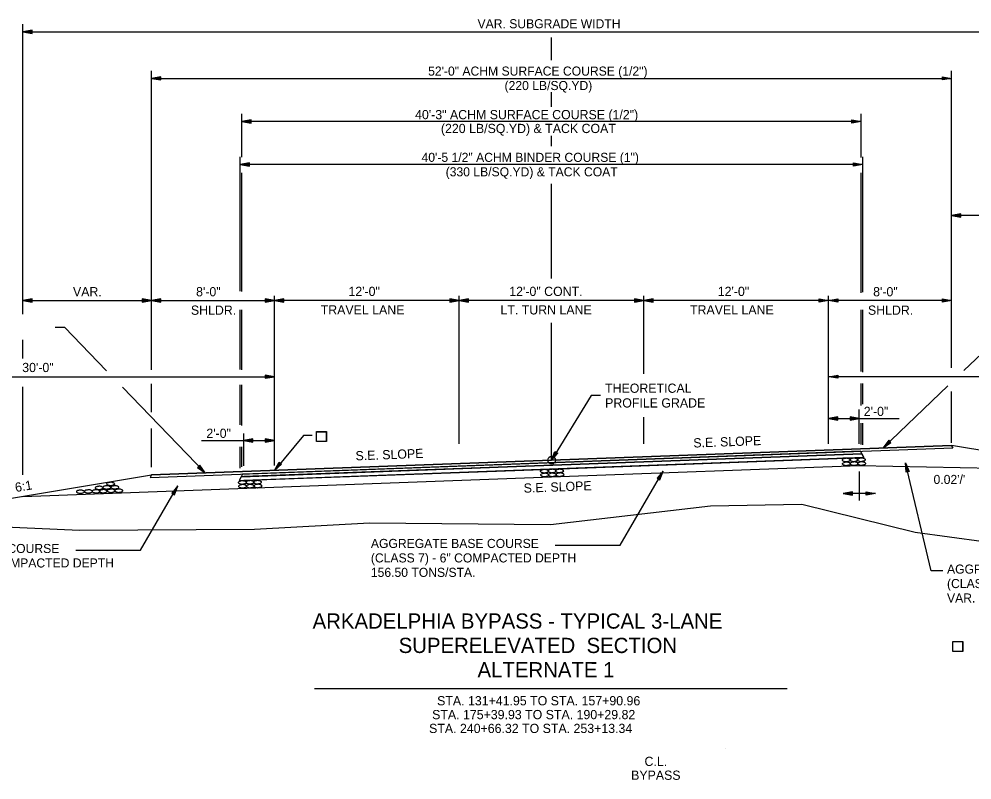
# Model space of a CAD drawing. Extents: x 1001270 to 1003428, y 1840152 to 1842912.
# Drawn here: x 1002308.4 to 1002370.3, y 1842569.6 to 1842619.1 of the extents above; entities that cross this region are included whole.
import ezdxf

# ---------------------------------------------------------------- set-up
doc = ezdxf.new("R2010")
doc.units = 0
for name, color, linetype in [('1', 7, 'Continuous'), ('19', 7, 'Continuous'), ('G-Table-Minor', 7, 'Continuous'), ('Level 1', 7, 'Continuous')]:
    doc.layers.add(name, color=color, linetype=linetype)

# ---------------------------------------------------------------- blocks, each defined once
blk = doc.blocks.new('ROCKS')
at = {"layer": '1'}
blk.add_spline([(0.013, 0.06), (0.053, 0.053), (0.107, 0.033), (0.133, 0.013), (0.133, -0.007), (0.12, -0.033), (0.107, -0.04), (0.073, -0.053), (0.033, -0.067), (0.013, -0.067), (-0.02, -0.06), (-0.06, -0.053), (-0.087, -0.047), (-0.113, -0.02), (-0.113, -0.007), (-0.107, 0.02), (-0.087, 0.033), (-0.067, 0.047), (-0.033, 0.053), (-0.02, 0.06), (0.013, 0.06)], degree=3, dxfattribs=at)
blk = doc.blocks.new('4TO1 ABC')
at = {"layer": '1', "xscale": 0.1312491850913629, "yscale": 0.1312491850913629, "rotation": 180}
for p in [(0.00175, -0.00875), (-0.03325, -0.0385), (-0.016625, -0.023625), (0, -0.0385), (0.018375, -0.023625), (0.034125, -0.04025), (0.051625, -0.025375), (0.06475, -0.04025), (0.098, -0.04025), (0.133, -0.041125)]:
    blk.add_blockref('ROCKS', p, dxfattribs=at)

msp = doc.modelspace()

# ---------------------------------------------------------------- linework, layer by layer
at = {"layer": '19'}
for p, q in [((1002308.637, 1842599.91), (1002308.637, 1842618.76)), ((1002309.237, 1842618.365), (1002308.637, 1842618.26)), ((1002308.637, 1842618.26), (1002378.71, 1842618.26)), ((1002308.637, 1842618.26), (1002309.237, 1842618.155)), ((1002309.237, 1842618.31), (1002308.797, 1842618.275)), ((1002308.797, 1842618.245), (1002309.237, 1842618.205)), ((1002309.237, 1842618.155), (1002309.237, 1842618.365)), ((1002342.992, 1842616.409), (1002342.992, 1842617.891)), ((1002316.992, 1842598.095), (1002316.992, 1842615.733)), ((1002368.992, 1842597.704), (1002368.992, 1842615.733)), ((1002317.592, 1842615.338), (1002316.992, 1842615.233)), ((1002316.992, 1842615.233), (1002317.592, 1842615.128)), ((1002316.992, 1842615.233), (1002368.992, 1842615.233)), ((1002317.592, 1842615.283), (1002317.152, 1842615.248)), ((1002317.152, 1842615.218), (1002317.592, 1842615.178)), ((1002317.592, 1842615.128), (1002317.592, 1842615.338)), ((1002368.392, 1842615.128), (1002368.392, 1842615.338)), ((1002368.392, 1842615.338), (1002368.992, 1842615.233)), ((1002368.392, 1842615.283), (1002368.832, 1842615.248)), ((1002368.992, 1842615.233), (1002368.392, 1842615.128)), ((1002368.832, 1842615.218), (1002368.392, 1842615.178)), ((1002342.992, 1842613.372), (1002342.992, 1842614.336)), ((1002322.864, 1842610.118), (1002322.864, 1842612.926)), ((1002363.119, 1842610.079), (1002363.119, 1842612.926)), ((1002323.464, 1842612.531), (1002322.864, 1842612.426)), ((1002322.864, 1842612.426), (1002323.464, 1842612.321)), ((1002363.119, 1842612.426), (1002322.864, 1842612.426)), ((1002323.464, 1842612.476), (1002323.024, 1842612.441)), ((1002323.024, 1842612.411), (1002323.464, 1842612.371)), ((1002323.464, 1842612.321), (1002323.464, 1842612.531)), ((1002362.519, 1842612.321), (1002362.519, 1842612.531)), ((1002362.519, 1842612.531), (1002363.119, 1842612.426)), ((1002362.519, 1842612.476), (1002362.959, 1842612.441)), ((1002363.119, 1842612.426), (1002362.519, 1842612.321)), ((1002362.959, 1842612.411), (1002362.519, 1842612.371)), ((1002342.992, 1842610.821), (1002342.992, 1842611.5)), ((1002322.758, 1842601.407), (1002322.758, 1842610.127)), ((1002363.226, 1842601.334), (1002363.226, 1842610.127)), ((1002323.358, 1842609.732), (1002322.758, 1842609.627)), ((1002322.758, 1842609.627), (1002323.358, 1842609.522)), ((1002363.226, 1842609.627), (1002322.758, 1842609.627)), ((1002323.358, 1842609.677), (1002322.918, 1842609.642)), ((1002322.918, 1842609.612), (1002323.358, 1842609.572)), ((1002323.358, 1842609.522), (1002323.358, 1842609.732)), ((1002362.626, 1842609.522), (1002362.626, 1842609.732)), ((1002362.626, 1842609.732), (1002363.226, 1842609.627)), ((1002362.626, 1842609.677), (1002363.066, 1842609.642)), ((1002363.226, 1842609.627), (1002362.626, 1842609.522)), ((1002363.066, 1842609.612), (1002362.626, 1842609.572)), ((1002322.864, 1842601.383), (1002322.864, 1842609.094)), ((1002363.119, 1842601.286), (1002363.119, 1842609.094)), ((1002342.992, 1842602.217), (1002342.992, 1842608.384)), ((1002369.592, 1842606.423), (1002368.992, 1842606.318)), ((1002369.592, 1842606.368), (1002369.152, 1842606.333)), ((1002369.592, 1842606.213), (1002369.592, 1842606.423)), ((1002378.71, 1842606.318), (1002368.992, 1842606.318)), ((1002368.992, 1842606.318), (1002369.592, 1842606.213)), ((1002369.152, 1842606.303), (1002369.592, 1842606.263)), ((1002377.255, 1842603.38), (1002369.786, 1842596.23)), ((1002309.236, 1842600.889), (1002308.636, 1842600.784)), ((1002309.236, 1842600.834), (1002308.796, 1842600.799)), ((1002309.236, 1842600.679), (1002309.236, 1842600.889)), ((1002316.392, 1842600.889), (1002316.392, 1842600.679)), ((1002316.992, 1842600.784), (1002316.392, 1842600.889)), ((1002316.832, 1842600.799), (1002316.392, 1842600.834)), ((1002316.992, 1842596.29), (1002316.992, 1842601.084)), ((1002317.592, 1842600.889), (1002316.992, 1842600.784)), ((1002317.592, 1842600.834), (1002317.152, 1842600.799)), ((1002317.592, 1842600.679), (1002317.592, 1842600.889)), ((1002324.392, 1842600.889), (1002324.392, 1842600.679)), ((1002324.992, 1842600.784), (1002324.392, 1842600.889)), ((1002324.832, 1842600.799), (1002324.392, 1842600.834)), ((1002324.992, 1842590.065), (1002324.992, 1842601.084)), ((1002325.592, 1842600.889), (1002324.992, 1842600.784)), ((1002325.592, 1842600.834), (1002325.152, 1842600.799)), ((1002325.592, 1842600.679), (1002325.592, 1842600.889)), ((1002336.392, 1842600.889), (1002336.392, 1842600.679)), ((1002336.992, 1842600.784), (1002336.392, 1842600.889)), ((1002336.832, 1842600.799), (1002336.392, 1842600.834)), ((1002336.992, 1842591.469), (1002336.992, 1842601.084)), ((1002337.592, 1842600.889), (1002336.992, 1842600.784)), ((1002337.592, 1842600.834), (1002337.152, 1842600.799)), ((1002337.592, 1842600.679), (1002337.592, 1842600.889)), ((1002348.392, 1842600.889), (1002348.392, 1842600.679)), ((1002348.992, 1842600.784), (1002348.392, 1842600.889)), ((1002348.832, 1842600.799), (1002348.392, 1842600.834)), ((1002348.992, 1842596.027), (1002348.992, 1842601.084)), ((1002349.592, 1842600.889), (1002348.992, 1842600.784)), ((1002349.592, 1842600.834), (1002349.152, 1842600.799)), ((1002349.592, 1842600.679), (1002349.592, 1842600.889)), ((1002360.392, 1842600.679), (1002360.392, 1842600.889)), ((1002360.392, 1842600.889), (1002360.992, 1842600.784)), ((1002360.392, 1842600.834), (1002360.832, 1842600.799)), ((1002360.992, 1842591.469), (1002360.992, 1842601.084)), ((1002360.992, 1842600.784), (1002361.592, 1842600.889)), ((1002361.152, 1842600.799), (1002361.592, 1842600.834)), ((1002361.592, 1842600.889), (1002361.592, 1842600.679)), ((1002368.392, 1842600.679), (1002368.392, 1842600.889)), ((1002368.392, 1842600.889), (1002368.992, 1842600.784)), ((1002368.392, 1842600.834), (1002368.832, 1842600.799)), ((1002368.992, 1842596.416), (1002368.992, 1842601.084)), ((1002308.636, 1842600.784), (1002309.236, 1842600.679)), ((1002308.637, 1842600.784), (1002324.992, 1842600.784)), ((1002308.796, 1842600.769), (1002309.236, 1842600.729)), ((1002316.392, 1842600.679), (1002316.992, 1842600.784)), ((1002316.392, 1842600.729), (1002316.832, 1842600.769)), ((1002316.992, 1842600.784), (1002317.592, 1842600.679)), ((1002317.152, 1842600.769), (1002317.592, 1842600.729)), ((1002322.758, 1842596.313), (1002322.758, 1842600.194)), ((1002322.864, 1842596.284), (1002322.864, 1842600.194)), ((1002324.392, 1842600.679), (1002324.992, 1842600.784)), ((1002324.392, 1842600.729), (1002324.832, 1842600.769)), ((1002324.992, 1842600.784), (1002325.592, 1842600.679)), ((1002336.992, 1842600.784), (1002324.992, 1842600.784)), ((1002325.152, 1842600.769), (1002325.592, 1842600.729)), ((1002336.392, 1842600.679), (1002336.992, 1842600.784)), ((1002336.392, 1842600.729), (1002336.832, 1842600.769)), ((1002348.992, 1842600.784), (1002336.992, 1842600.784)), ((1002336.992, 1842600.784), (1002337.592, 1842600.679)), ((1002337.152, 1842600.769), (1002337.592, 1842600.729)), ((1002348.392, 1842600.679), (1002348.992, 1842600.784)), ((1002348.392, 1842600.729), (1002348.832, 1842600.769)), ((1002360.992, 1842600.784), (1002348.992, 1842600.784)), ((1002348.992, 1842600.784), (1002349.592, 1842600.679)), ((1002349.152, 1842600.769), (1002349.592, 1842600.729)), ((1002360.992, 1842600.784), (1002360.392, 1842600.679)), ((1002360.832, 1842600.769), (1002360.392, 1842600.729)), ((1002368.992, 1842600.784), (1002360.992, 1842600.784)), ((1002361.592, 1842600.679), (1002360.992, 1842600.784)), ((1002361.592, 1842600.729), (1002361.152, 1842600.769)), ((1002363.119, 1842596.169), (1002363.119, 1842600.194)), ((1002363.226, 1842596.14), (1002363.226, 1842600.194)), ((1002368.992, 1842600.784), (1002368.392, 1842600.679)), ((1002368.832, 1842600.769), (1002368.392, 1842600.729)), ((1002342.992, 1842590.412), (1002342.992, 1842599.341)), ((1002308.637, 1842597.021), (1002308.637, 1842598.235)), ((1002294.986, 1842595.836), (1002324.986, 1842595.836)), ((1002324.386, 1842595.941), (1002324.386, 1842595.731)), ((1002324.986, 1842595.836), (1002324.386, 1842595.941)), ((1002324.826, 1842595.851), (1002324.386, 1842595.886)), ((1002324.386, 1842595.731), (1002324.986, 1842595.836)), ((1002361.009, 1842595.836), (1002361.609, 1842595.941)), ((1002391.009, 1842595.836), (1002361.009, 1842595.836)), ((1002361.609, 1842595.731), (1002361.009, 1842595.836)), ((1002361.169, 1842595.851), (1002361.609, 1842595.886)), ((1002361.609, 1842595.941), (1002361.609, 1842595.731)), ((1002316.992, 1842593.539), (1002316.992, 1842595.371)), ((1002322.758, 1842592.701), (1002322.758, 1842595.302)), ((1002322.864, 1842592.672), (1002322.864, 1842595.302)), ((1002324.386, 1842595.781), (1002324.826, 1842595.821)), ((1002361.609, 1842595.781), (1002361.169, 1842595.821)), ((1002363.119, 1842593.973), (1002363.119, 1842595.388)), ((1002363.226, 1842594.059), (1002363.226, 1842595.388)), ((1002368.754, 1842595.241), (1002364.542, 1842591.209)), ((1002308.637, 1842589.451), (1002308.637, 1842595.172)), ((1002368.992, 1842591.535), (1002368.992, 1842594.882)), ((1002362.992, 1842591.469), (1002362.992, 1842593.707)), ((1002348.992, 1842591.469), (1002348.992, 1842593.213)), ((1002361.592, 1842593.221), (1002360.992, 1842593.116)), ((1002360.992, 1842593.116), (1002365.578, 1842593.116)), ((1002360.992, 1842593.116), (1002361.592, 1842593.011)), ((1002361.592, 1842593.166), (1002361.152, 1842593.131)), ((1002361.152, 1842593.101), (1002361.592, 1842593.061)), ((1002361.592, 1842593.011), (1002361.592, 1842593.221)), ((1002362.392, 1842593.221), (1002362.392, 1842593.011)), ((1002362.992, 1842593.116), (1002362.392, 1842593.221)), ((1002362.832, 1842593.131), (1002362.392, 1842593.166)), ((1002362.392, 1842593.011), (1002362.992, 1842593.116)), ((1002362.392, 1842593.061), (1002362.832, 1842593.101)), ((1002363.119, 1842591.43), (1002363.119, 1842592.817)), ((1002363.226, 1842591.401), (1002363.226, 1842592.817)), ((1002316.992, 1842589.956), (1002316.992, 1842592.47)), ((1002322.992, 1842590.045), (1002322.992, 1842592.139)), ((1002320.254, 1842591.692), (1002324.992, 1842591.692)), ((1002323.592, 1842591.797), (1002322.992, 1842591.692)), ((1002322.992, 1842591.692), (1002323.592, 1842591.587)), ((1002323.592, 1842591.742), (1002323.152, 1842591.707)), ((1002323.152, 1842591.677), (1002323.592, 1842591.637)), ((1002323.592, 1842591.587), (1002323.592, 1842591.797)), ((1002324.392, 1842591.797), (1002324.392, 1842591.587)), ((1002324.992, 1842591.692), (1002324.392, 1842591.797)), ((1002324.832, 1842591.707), (1002324.392, 1842591.742)), ((1002324.392, 1842591.587), (1002324.992, 1842591.692)), ((1002324.392, 1842591.637), (1002324.832, 1842591.677)), ((1002364.903, 1842591.7), (1002364.542, 1842591.209)), ((1002364.542, 1842591.209), (1002365.048, 1842591.548)), ((1002364.941, 1842591.66), (1002364.647, 1842591.33)), ((1002364.668, 1842591.309), (1002365.013, 1842591.584)), ((1002365.048, 1842591.548), (1002364.903, 1842591.7)), ((1002322.758, 1842589.899), (1002322.758, 1842591.286)), ((1002322.864, 1842589.985), (1002322.864, 1842591.286)), ((1002342.992, 1842590.412), (1002343.215, 1842590.978)), ((1002343.066, 1842590.552), (1002343.258, 1842590.946)), ((1002343.352, 1842590.89), (1002343.088, 1842590.541)), ((1002343.215, 1842590.978), (1002343.393, 1842590.869)), ((1002363.074, 1842590.988), (1002363.155, 1842590.824)), ((1002390.992, 1842587.707), (1002368.992, 1842591.374)), ((1002368.992, 1842591.374), (1002369.074, 1842591.21)), ((1002363.278, 1842590.579), (1002322.992, 1842589.089)), ((1002324.992, 1842589.746), (1002325.29, 1842590.277)), ((1002325.29, 1842590.277), (1002325.451, 1842590.144)), ((1002343.393, 1842590.869), (1002342.992, 1842590.412)), ((1002362.211, 1842590.543), (1002361.913, 1842590.531)), ((1002363.155, 1842590.824), (1002363.278, 1842590.579)), ((1002363.278, 1842590.579), (1002363.278, 1842590.579)), ((1002320.142, 1842590.083), (1002319.991, 1842589.938)), ((1002319.991, 1842589.938), (1002320.483, 1842589.579)), ((1002320.03, 1842589.976), (1002320.361, 1842589.684)), ((1002320.383, 1842589.704), (1002320.106, 1842590.049)), ((1002320.483, 1842589.579), (1002320.142, 1842590.083)), ((1002325.451, 1842590.144), (1002324.992, 1842589.746)), ((1002325.084, 1842589.875), (1002325.328, 1842590.239)), ((1002325.414, 1842590.171), (1002325.105, 1842589.861)), ((1002347.445, 1842584.891), (1002350.244, 1842589.697)), ((1002350.244, 1842589.697), (1002349.851, 1842589.231)), ((1002350.033, 1842589.127), (1002350.244, 1842589.697)), ((1002362.992, 1842590.068), (1002378.71, 1842589.754)), ((1002362.992, 1842589.676), (1002362.992, 1842587.793)), ((1002367.657, 1842583.222), (1002365.997, 1842590.229)), ((1002366.033, 1842589.622), (1002365.997, 1842590.229)), ((1002365.997, 1842590.229), (1002366.237, 1842589.669)), ((1002366.082, 1842589.634), (1002366.018, 1842590.07)), ((1002366.237, 1842589.669), (1002366.033, 1842589.622)), ((1002366.045, 1842590.077), (1002366.185, 1842589.66)), ((1002294.986, 1842585.782), (1002316.992, 1842589.45)), ((1002316.992, 1842589.45), (1002316.907, 1842589.28)), ((1002322.822, 1842589.332), (1002322.695, 1842589.077)), ((1002322.907, 1842589.502), (1002322.822, 1842589.332)), ((1002322.992, 1842589.089), (1002322.992, 1842589.089)), ((1002322.992, 1842589.089), (1002322.992, 1842589.089)), ((1002349.851, 1842589.231), (1002350.033, 1842589.127)), ((1002350.153, 1842589.565), (1002349.899, 1842589.207)), ((1002349.99, 1842589.152), (1002350.177, 1842589.551)), ((1002316.282, 1842584.564), (1002318.709, 1842588.731)), ((1002318.709, 1842588.731), (1002318.317, 1842588.265)), ((1002318.618, 1842588.599), (1002318.364, 1842588.241)), ((1002318.455, 1842588.186), (1002318.643, 1842588.585)), ((1002318.498, 1842588.161), (1002318.709, 1842588.731)), ((1002318.317, 1842588.265), (1002318.498, 1842588.161)), ((1002362.544, 1842588.35), (1002361.944, 1842588.245)), ((1002361.944, 1842588.245), (1002362.544, 1842588.14)), ((1002364.039, 1842588.245), (1002361.944, 1842588.245)), ((1002362.544, 1842588.295), (1002362.104, 1842588.26)), ((1002362.104, 1842588.23), (1002362.544, 1842588.19)), ((1002362.544, 1842588.14), (1002362.544, 1842588.35)), ((1002363.439, 1842588.14), (1002363.439, 1842588.35)), ((1002363.439, 1842588.35), (1002364.039, 1842588.245)), ((1002363.439, 1842588.295), (1002363.879, 1842588.26)), ((1002364.039, 1842588.245), (1002363.439, 1842588.14)), ((1002363.879, 1842588.23), (1002363.439, 1842588.19)), ((1002304.337, 1842586.209), (1002312.324, 1842585.864)), ((1002312.324, 1842585.864), (1002323.688, 1842585.919)), ((1002343.231, 1842584.891), (1002347.445, 1842584.891)), ((1002312.068, 1842584.564), (1002316.282, 1842584.564)), ((1002368.424, 1842583.222), (1002367.657, 1842583.222)), ((1002327.589, 1842575.565), (1002358.306, 1842575.565))]:
    msp.add_line(p, q, dxfattribs=at)
for points in [[(1002310.736, 1842599.052), (1002311.336, 1842599.052), (1002314.082, 1842596.207)], [(1002315.106, 1842595.148), (1002320.483, 1842589.579)], [(1002346.175, 1842594.611), (1002345.575, 1842594.61), (1002342.992, 1842590.412)], [(1002328.356, 1842591.62), (1002327.715, 1842591.62), (1002327.715, 1842592.261), (1002328.356, 1842592.261), (1002328.356, 1842591.62)], [(1002327.719, 1842591.623), (1002327.719, 1842592.265), (1002328.36, 1842592.265), (1002328.36, 1842591.623), (1002327.719, 1842591.623)], [(1002327.435, 1842592.01), (1002326.865, 1842592.01), (1002324.992, 1842589.746)], [(1002316.907, 1842589.28), (1002369.074, 1842591.21)], [(1002316.992, 1842589.45), (1002342.992, 1842590.412), (1002368.992, 1842591.374)], [(1002363.278, 1842590.579), (1002363.155, 1842590.824), (1002322.992, 1842589.339), (1002322.822, 1842589.332), (1002322.695, 1842589.077)], [(1002322.695, 1842589.077), (1002342.992, 1842589.828), (1002363.278, 1842590.579)], [(1002322.822, 1842589.332), (1002342.992, 1842590.078), (1002363.155, 1842590.824)], [(1002308.637, 1842588.057), (1002342.992, 1842589.328), (1002362.992, 1842590.068)], [(1002322.695, 1842589.077), (1002322.992, 1842589.089)], [(1002323.688, 1842585.919), (1002331.168, 1842586.341), (1002331.168, 1842586.341), (1002342.916, 1842586.233), (1002353.315, 1842587.45)], [(1002353.315, 1842587.45), (1002359.249, 1842587.555), (1002366.621, 1842585.727), (1002371.093, 1842585.124), (1002377.579, 1842584.498), (1002395.136, 1842584.38), (1002405.497, 1842582.872), (1002418.132, 1842582.941)], [(1002369.709, 1842577.97), (1002369.067, 1842577.97), (1002369.067, 1842578.611), (1002369.709, 1842578.611), (1002369.709, 1842577.97)], [(1002369.071, 1842577.973), (1002369.071, 1842578.614), (1002369.712, 1842578.614), (1002369.712, 1842577.973), (1002369.071, 1842577.973)]]:
    msp.add_lwpolyline(points, dxfattribs=at)
for points in [[(1002316.992, 1842589.45), (1002316.907, 1842589.28), (1002369.074, 1842591.21), (1002368.992, 1842591.374)], [(1002322.992, 1842589.505), (1002322.907, 1842589.502), (1002322.822, 1842589.332), (1002322.992, 1842589.339), (1002363.155, 1842590.824), (1002363.074, 1842590.988)]]:
    msp.add_lwpolyline(points, close=True, dxfattribs=at)
msp.add_circle((1002342.996, 1842590.409), 0.25, dxfattribs=at)
at = {"layer": 'G-Table-Minor'}
msp.add_line((1002354.288, 1842571.694), (1002354.288, 1842571.694), dxfattribs=at)
msp.add_line((1002354.288, 1842571.694), (1002354.288, 1842571.694), dxfattribs=at)

# ---------------------------------------------------------------- block references
at = {"layer": '19', "xscale": 14.999970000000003, "yscale": -14.999970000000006, "rotation": -179.4346871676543}
msp.add_blockref('4TO1 ABC', (1002314.347, 1842588.991), dxfattribs=at)
at = {"layer": 'Level 1', "xscale": 2.0116542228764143, "yscale": -2.0116542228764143, "rotation": -178.25539552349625}
for p in [(1002362.163, 1842590.429), (1002362.178, 1842590.181), (1002362.658, 1842590.439), (1002362.674, 1842590.191), (1002363.142, 1842590.444), (1002363.166, 1842590.2), (1002342.553, 1842589.703), (1002343.049, 1842589.712), (1002343.532, 1842589.717), (1002322.921, 1842588.967), (1002323.417, 1842588.977), (1002323.901, 1842588.982), (1002342.568, 1842589.455), (1002343.064, 1842589.465), (1002343.557, 1842589.473), (1002322.937, 1842588.719), (1002323.433, 1842588.729), (1002323.925, 1842588.737)]:
    msp.add_blockref('ROCKS', p, dxfattribs=at)

# ---------------------------------------------------------------- texts
at = {"layer": '19'}
for s, height, p in [('VAR. SUBGRADE WIDTH', 0.59001, (1002338.183, 1842618.491)), ('52\'-0" ACHM SURFACE COURSE (1/2")', 0.59001, (1002334.973, 1842615.412)), ('(220 LB/SQ.YD)', 0.59001, (1002339.94, 1842614.472)), ('40\'-3" ACHM SURFACE COURSE (1/2")', 0.6, (1002334.125, 1842612.577)), ('(220 LB/SQ.YD) & TACK COAT', 0.6, (1002335.804, 1842611.677)), ('40\'-5 1/2" ACHM BINDER COURSE (1")', 0.59001, (1002334.545, 1842609.803)), ('(330 LB/SQ.YD) & TACK COAT', 0.59001, (1002336.113, 1842608.863)), ('VAR.', 0.6, (1002311.892, 1842601.063)), ('8\'-0"', 0.6, (1002319.893, 1842601.063)), ('12\'-0"', 0.6, (1002329.794, 1842601.084)), ('12\'-0" CONT.', 0.6, (1002340.247, 1842601.084)), ('12\'-0"', 0.6, (1002353.794, 1842601.084)), ('8\'-0"', 0.6, (1002363.893, 1842601.063)), ('SHLDR.', 0.6, (1002319.556, 1842599.863)), ('TRAVEL LANE', 0.6, (1002327.992, 1842599.884)), ('LT. TURN LANE', 0.6, (1002339.675, 1842599.884)), ('TRAVEL LANE', 0.6, (1002351.992, 1842599.884)), ('SHLDR.', 0.6, (1002363.556, 1842599.863)), ('30\'-0"', 0.6, (1002308.595, 1842596.136)), ('THEORETICAL', 0.6, (1002346.475, 1842594.789)), ('PROFILE GRADE', 0.6, (1002346.475, 1842593.833)), ('2\'-0"', 0.6, (1002363.283, 1842593.279)), ('2\'-0"', 0.6, (1002320.562, 1842591.858)), ("0.02'/'", 0.59, (1002367.819, 1842588.861)), ('C.L.', 0.6, (1002349.035, 1842570.527)), ('BYPASS', 0.6, (1002348.166, 1842569.627))]:
    msp.add_text(s, height=height, dxfattribs=at).set_placement(p)
for s, height, rotation, p in [('S.E. SLOPE', 0.6, 2.11898, (1002352.218, 1842591.228)), ('S.E. SLOPE', 0.6, 2.11898, (1002330.265, 1842590.394)), ('6:1', 0.6, 9.39232, (1002308.178, 1842588.333)), ('S.E. SLOPE', 0.6, 2.11898, (1002341.194, 1842588.292)), ('AGGREGATE BASE COURSE', 0.59001, 359.99538, (1002300.09, 1842584.373)), ('AGGREGATE BASE COURSE', 0.59001, 359.99538, (1002331.253, 1842584.7)), ('(CLASS 7) - 6" COMPACTED DEPTH', 0.59001, 359.99538, (1002331.252, 1842583.76)), ('(CLASS 7) - VAR. COMPACTED DEPTH', 0.59001, 359.99538, (1002300.089, 1842583.433)), ('AGGREGATE BASE COURSE', 0.59001, 359.99538, (1002368.694, 1842583.032)), ('156.50 TONS/STA.', 0.59001, 359.99538, (1002331.252, 1842582.82)), ('(CLASS 7) - VAR. COMPACTED DEPTH', 0.59001, 359.99538, (1002368.694, 1842582.092)), ('VAR. TONS/STA.', 0.59001, 359.99538, (1002368.694, 1842581.152)), ('ARKADELPHIA BYPASS - TYPICAL 3-LANE ', 0.98999, 359.99538, (1002327.464, 1842579.457)), ('SUPERELEVATED  SECTION', 0.98999, 359.99538, (1002333.057, 1842577.872)), ('ALTERNATE 1', 0.98999, 359.99538, (1002338.182, 1842576.288)), ('STA. 131+41.95 TO STA. 157+90.96', 0.6, 0.00462, (1002335.557, 1842574.468)), ('STA. 175+39.93 TO STA. 190+29.82', 0.6, 0.00462, (1002335.233, 1842573.568)), ('STA. 240+66.32 TO STA. 253+13.34', 0.6, 0.00462, (1002335.035, 1842572.668))]:
    msp.add_text(s, height=height, rotation=rotation, dxfattribs=at).set_placement(p)

doc.saveas('drawing.dxf')
